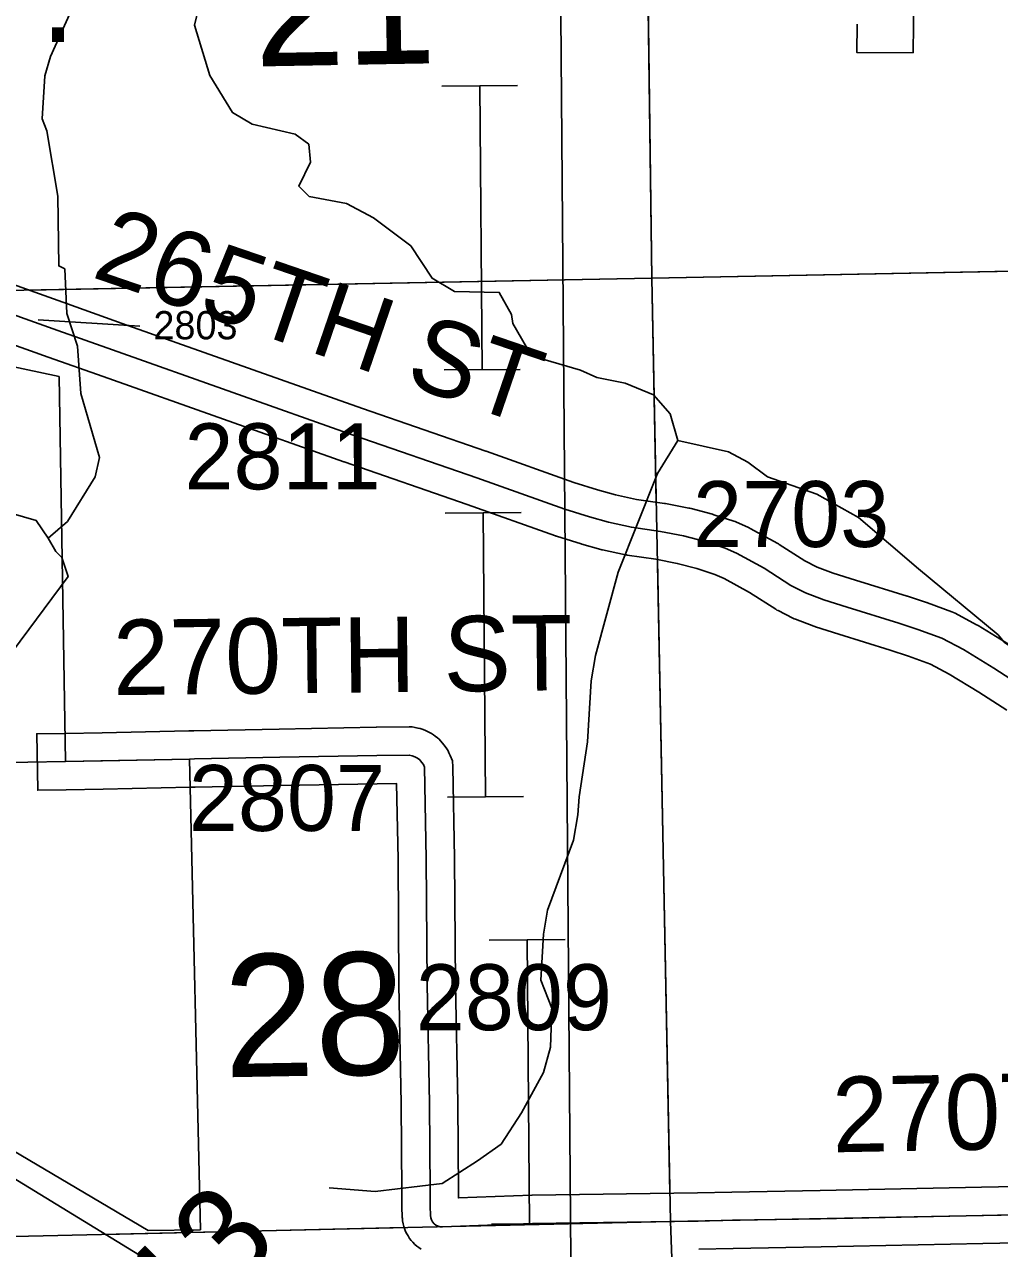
# Model space of a CAD drawing. Extents: x 23.6 to 68.7, y -63 to -29.
# Drawn here: x 47.009 to 48.044, y -50.568 to -49.268 of the extents above; entities that cross this region are included whole.
import ezdxf

# ---------------------------------------------------------------- set-up
doc = ezdxf.new("R2010")
doc.units = 0
for name, color, linetype in [('tdCoCityStreetMajor', 7, 'Continuous'), ('tdCoCorpBndry', 7, 'Continuous'), ('tdCoCorpPopTxt', 7, 'Continuous'), ('tdCoHydroRiver', 7, 'Continuous'), ('tdCoPipe', 7, 'Continuous'), ('tdCoSecRdNmbr', 7, 'Continuous'), ('tdCoSecRdTxt', 7, 'Continuous'), ('tdCoSecRteBand', 7, 'Continuous'), ('tdCoSecRteCL', 7, 'Continuous'), ('tdCoSectLine', 7, 'Continuous'), ('tdCoSectLinePart', 7, 'Continuous'), ('tdCoSectNmbr', 7, 'Continuous'), ('tdCoSurfGravel', 7, 'Continuous'), ('tdStHwyPriRefPost1', 7, 'Continuous')]:
    doc.layers.add(name, color=color, linetype=linetype)

msp = doc.modelspace()

# ---------------------------------------------------------------- linework, layer by layer
at = {"layer": 'tdCoCityStreetMajor'}
msp.add_lwpolyline([(46.9325, -50.0529), (47.0124, -50.0514), (47.0524, -50.0507)], dxfattribs=at)
at = {"layer": 'tdCoCorpBndry'}
msp.add_lwpolyline([(46.8095, -49.5915), (47.0456, -49.6419), (47.0524, -50.0507), (47.184, -50.048), (47.1957, -50.5478), (47.1403, -50.5485), (46.937, -50.4286)], dxfattribs=at)
msp.add_lwpolyline([(47.1214, -50.8004), (46.8344, -50.5559), (46.9417, -50.5533), (46.938, -50.4571), (47.194, -50.6134), (47.4984, -50.7957)], close=True, dxfattribs=at)
at = {"layer": 'tdCoHydroRiver'}
for points in [[(47.1144, -49.2111), (47.083, -49.2272), (47.0721, -49.2353), (47.0581, -49.2543), (47.0365, -49.3019), (47.0304, -49.3225), (47.0278, -49.3683), (47.0326, -49.3809), (47.0444, -49.4502), (47.0452, -49.5244), (47.0516, -49.5275), (47.0537, -49.5748), (47.0651, -49.6095), (47.0688, -49.6599), (47.0885, -49.7276), (47.084, -49.7482), (47.0545, -49.7958), (47.0342, -49.8134)], [(47.7024, -49.7098), (47.6942, -49.6815), (47.6766, -49.6611), (47.6465, -49.6488), (47.6164, -49.6429), (47.599, -49.6352), (47.553, -49.6215), (47.5419, -49.6105), (47.5274, -49.5854), (47.5257, -49.576), (47.5128, -49.5524), (47.4654, -49.5514), (47.4416, -49.5374), (47.4191, -49.503), (47.3793, -49.4734), (47.3508, -49.4579), (47.3112, -49.4505), (47.3, -49.4395), (47.3124, -49.4142), (47.3106, -49.3952), (47.2963, -49.3843), (47.2504, -49.3738), (47.2297, -49.3614), (47.2056, -49.3222), (47.1893, -49.2687), (47.1938, -49.2497)], [(47.7024, -49.7098), (47.6807, -49.7448), (47.6392, -49.8494), (47.6149, -49.9381), (47.6105, -49.965), (47.6064, -50.0297), (47.5976, -50.0882), (47.5962, -50.1072), (47.5918, -50.1341), (47.5642, -50.2086), (47.5597, -50.2339), (47.5571, -50.2828), (47.5685, -50.3127), (47.5673, -50.3538), (47.5597, -50.3807), (47.5365, -50.4236), (47.5148, -50.4569), (47.4897, -50.4746), (47.4521, -50.4987), (47.3812, -50.5073), (47.3322, -50.5032)], [(48.4058, -50.3777), (48.3898, -50.3589), (48.3545, -50.3041), (48.2986, -50.2416), (48.2665, -50.1961), (48.2552, -50.1726), (48.2488, -50.1663), (48.2183, -50.1209), (48.157, -50.0032), (48.1299, -49.9782), (48.0488, -49.9238), (48.0424, -49.916), (47.958, -49.8459), (47.8943, -49.7914), (47.8498, -49.7666), (47.7975, -49.7482), (47.7768, -49.7327), (47.7562, -49.7218), (47.7024, -49.7098)], [(47.0342, -49.8134), (47.0214, -49.7946), (46.9944, -49.787), (46.9835, -49.7935), (46.9807, -49.8266), (46.9777, -49.8456), (46.9512, -49.8743), (46.9484, -49.9107)], [(47.0342, -49.8134), (47.0423, -49.8275), (47.0486, -49.8338), (47.0552, -49.8542), (46.9961, -49.9338), (46.9681, -49.9783), (46.9355, -50.0292), (46.9152, -50.0436)]]:
    msp.add_lwpolyline(points, dxfattribs=at)
at = {"layer": 'tdCoPipe'}
for p, q in [((47.4519, -49.3335), (47.5324, -49.3328)), ((47.4543, -49.6348), (47.535, -49.6342)), ((47.4556, -49.787), (47.5361, -49.7863)), ((47.458, -50.0883), (47.5387, -50.0877)), ((47.5022, -50.2405), (47.5828, -50.2398)), ((47.5047, -50.5418), (47.5853, -50.5412))]:
    msp.add_line(p, q, dxfattribs=at)
for points in [[(47.6047, -46.6586), (47.5572, -46.6597), (47.5935, -51.1509), (47.5318, -51.225), (47.5319, -51.3484), (47.5319, -51.3484), (47.6677, -51.41), (47.7455, -57.4574)], [(47.4922, -49.3332), (47.4947, -49.6345)], [(47.4959, -49.7867), (47.4983, -50.088)], [(47.5426, -50.2402), (47.545, -50.5415)]]:
    msp.add_lwpolyline(points, dxfattribs=at)
at = {"layer": 'tdCoSecRdNmbr'}
msp.add_line((47.1312, -49.5883), (47.0235, -49.5816), dxfattribs=at)
at = {"layer": 'tdCoSecRteBand'}
for points in [[(47.9532, -49.2205), (47.9527, -49.2682), (47.9524, -49.2982)], [(47.9524, -49.2982), (47.8924, -49.2976), (47.8927, -49.2676)], [(46.8977, -49.5087), (47.0544, -49.5646), (47.1125, -49.5853), (47.3678, -49.6758), (47.4987, -49.7211), (47.4988, -49.7212), (47.4989, -49.7212), (47.5921, -49.7543), (47.6172, -49.7622), (47.6361, -49.7675), (47.6584, -49.7722), (47.6882, -49.7765), (47.6889, -49.7766), (47.6895, -49.7767), (47.7142, -49.7814), (47.7153, -49.7816), (47.7165, -49.7819), (47.7391, -49.7881), (47.7399, -49.7883), (47.7406, -49.7885), (47.7618, -49.7954), (47.7632, -49.7959), (47.7646, -49.7965), (47.7769, -49.8019), (47.7781, -49.8025), (47.7793, -49.8031), (47.8084, -49.8191), (47.8092, -49.8196), (47.81, -49.8201), (47.8374, -49.8376), (47.8502, -49.8441), (47.8673, -49.8506), (47.8911, -49.858), (47.8911, -49.858), (47.8911, -49.858), (47.9458, -49.875), (47.9461, -49.875), (47.9463, -49.8751), (47.9665, -49.8818), (47.967, -49.8819), (47.9675, -49.8821), (47.9931, -49.8915), (47.9951, -49.8922), (47.9969, -49.8932), (48.0196, -49.9053), (48.0204, -49.9057), (48.0211, -49.9061), (48.0534, -49.9259)], [(48.0516, -49.9961), (48.0218, -49.9769), (47.9906, -49.9578), (47.9706, -49.9471), (47.9473, -49.9386), (47.9278, -49.9322), (47.8733, -49.9153), (47.8487, -49.9076), (47.8478, -49.9073), (47.8469, -49.907), (47.8274, -49.8996), (47.8259, -49.899), (47.8245, -49.8983), (47.8089, -49.8904), (47.8076, -49.8898), (47.8064, -49.889), (47.7786, -49.8712), (47.7515, -49.8563), (47.7418, -49.852), (47.7227, -49.8458), (47.7018, -49.8402), (47.679, -49.8358), (47.6488, -49.8315), (47.6478, -49.8313), (47.6468, -49.8311), (47.6226, -49.8259), (47.6217, -49.8257), (47.6208, -49.8255), (47.6006, -49.8198), (47.6002, -49.8197), (47.5998, -49.8196), (47.5736, -49.8114), (47.5731, -49.8113), (47.5725, -49.8111), (47.4789, -49.7778), (47.3481, -49.7325), (47.348, -49.7324), (47.3479, -49.7324), (47.0924, -49.6419), (47.0924, -49.6419), (47.0923, -49.6419), (47.0342, -49.6211), (46.8777, -49.5652)], [(47.4299, -50.5686), (47.4275, -50.5668), (47.4255, -50.5653), (47.4231, -50.5634), (47.4211, -50.5611), (47.4195, -50.5593), (47.4175, -50.557), (47.416, -50.5543), (47.4148, -50.5522), (47.4133, -50.5496), (47.4123, -50.5467), (47.4116, -50.5443), (47.4107, -50.5414), (47.4103, -50.5384), (47.41, -50.536), (47.4099, -50.5349), (47.4099, -50.5339), (47.4095, -50.5241), (47.4095, -50.5235), (47.4095, -50.5229), (47.4095, -50.5075), (47.4088, -50.4139), (47.4064, -50.2879), (47.4064, -50.2877), (47.4064, -50.2876), (47.4054, -50.1542), (47.4039, -50.074), (47.3832, -50.0742), (47.2806, -50.0761), (47.1901, -50.0779), (47.1846, -50.078), (47.0924, -50.08), (47.0923, -50.08), (47.0923, -50.08), (47.053, -50.0807), (47.023, -50.0812), (47.0219, -50.0212), (47.0519, -50.0207), (47.0912, -50.02), (47.1834, -50.018), (47.1888, -50.0179), (47.1888, -50.0179), (47.1888, -50.0179), (47.2794, -50.0161), (47.2794, -50.0161), (47.2794, -50.0161), (47.3822, -50.0143), (47.3823, -50.0143), (47.3824, -50.0143), (47.4171, -50.0138), (47.4203, -50.0138), (47.4235, -50.0145), (47.4266, -50.0151), (47.4289, -50.0156), (47.4311, -50.0164), (47.4339, -50.0175), (47.4361, -50.0183), (47.4382, -50.0195), (47.4409, -50.021), (47.4429, -50.0222), (47.4447, -50.0236), (47.4472, -50.0256), (47.449, -50.027), (47.4506, -50.0288), (47.4527, -50.031), (47.4542, -50.0328), (47.4555, -50.0347), (47.4573, -50.0373), (47.4585, -50.0393), (47.4595, -50.0414), (47.4608, -50.0442), (47.4634, -50.0499), (47.4635, -50.0561), (47.4654, -50.1532), (47.4654, -50.1534), (47.4654, -50.1535), (47.4664, -50.2869), (47.4688, -50.413), (47.4688, -50.4132), (47.4688, -50.4134), (47.4695, -50.5072), (47.4695, -50.5073), (47.4695, -50.5074), (47.4695, -50.5141), (47.5473, -50.5112), (47.5476, -50.5112), (47.5479, -50.5112), (47.7234, -50.5086), (47.7598, -50.5078), (47.7598, -50.5078), (47.7599, -50.5078), (47.8535, -50.5061), (48.0249, -50.5026), (48.1699, -50.4997)], [(48.1709, -50.5596), (48.0261, -50.5626), (48.0261, -50.5626), (48.0261, -50.5626), (47.8546, -50.5661), (47.8546, -50.5661), (47.8546, -50.5661), (47.761, -50.5677), (47.7246, -50.5686)]]:
    msp.add_lwpolyline(points, dxfattribs=at)
at = {"layer": 'tdCoSecRteCL'}
for points in [[(46.8876, -49.5369), (47.0443, -49.5929), (47.1024, -49.6136), (47.3579, -49.7041), (47.4889, -49.7495), (47.5826, -49.7828), (47.6087, -49.7909), (47.6289, -49.7966), (47.6531, -49.8018), (47.6839, -49.8062), (47.7086, -49.8109), (47.7313, -49.8171), (47.7525, -49.824), (47.7648, -49.8294), (47.7939, -49.8454), (47.8225, -49.8637), (47.8381, -49.8716), (47.8575, -49.879), (47.8822, -49.8866), (47.9369, -49.9036), (47.9572, -49.9103), (47.9828, -49.9197), (48.0055, -49.9317), (48.0378, -49.9515), (48.0679, -49.9709)], [(47.0524, -50.0507), (47.0918, -50.05), (47.184, -50.048), (47.1894, -50.0479), (47.28, -50.0461), (47.3828, -50.0443), (47.4174, -50.0438), (47.4205, -50.0445), (47.4233, -50.0456), (47.426, -50.0471), (47.4285, -50.049), (47.4305, -50.0513), (47.4323, -50.0539), (47.4335, -50.0567), (47.4354, -50.1538), (47.4364, -50.2873), (47.4388, -50.4136), (47.4395, -50.5074), (47.4395, -50.5229), (47.4399, -50.5327), (47.4401, -50.5351), (47.4409, -50.5374), (47.4421, -50.5396), (47.4437, -50.5414), (47.4457, -50.5429), (47.4479, -50.544), (47.4503, -50.5446), (47.4527, -50.5447), (47.5483, -50.5412), (47.7239, -50.5386), (47.7604, -50.5378), (47.854, -50.5361), (48.0255, -50.5326), (48.1705, -50.5296)]]:
    msp.add_lwpolyline(points, dxfattribs=at)
at = {"layer": 'tdCoSectLine'}
for points in [[(47.6616, -48.5433), (47.6748, -49.5372)], [(47.6748, -49.5372), (48.6762, -49.5179)], [(46.6744, -49.5566), (47.6748, -49.5372)], [(47.6748, -49.5372), (47.6946, -50.539)], [(47.6946, -50.539), (48.6917, -50.5199)], [(46.6878, -50.5621), (47.6946, -50.539)], [(47.6946, -50.539), (47.7309, -51.5361)]]:
    msp.add_lwpolyline(points, dxfattribs=at)
at = {"layer": 'tdCoSectLinePart'}
for points in [[(47.6686, -49.0685), (47.6748, -49.5372)], [(47.6748, -49.5372), (48.6461, -49.5184)], [(47.0136, -49.55), (47.6748, -49.5372)], [(47.6748, -49.5372), (47.6795, -49.7753)], [(47.6807, -49.8367), (47.694, -50.5085)], [(47.0944, -50.5528), (47.4118, -50.5455)]]:
    msp.add_lwpolyline(points, dxfattribs=at)
at = {"layer": 'tdCoSurfGravel'}
for points in [[(46.4274, -49.3397), (46.4381, -49.352), (46.4506, -49.3658), (46.4659, -49.3771), (46.4894, -49.3887), (46.5261, -49.4042), (46.661, -49.4578), (46.6751, -49.4632), (46.6972, -49.4718), (46.8876, -49.5369), (47.0443, -49.5929)], [(47.0443, -49.5929), (47.1024, -49.6136), (47.3579, -49.7041), (47.4889, -49.7495), (47.5826, -49.7828), (47.6087, -49.7909), (47.6289, -49.7966), (47.6531, -49.8018), (47.6839, -49.8062), (47.7086, -49.8109), (47.7313, -49.8171), (47.7525, -49.824), (47.7648, -49.8294), (47.7939, -49.8454), (47.8225, -49.8637), (47.8381, -49.8716), (47.8575, -49.879), (47.8822, -49.8866), (47.9369, -49.9036), (47.9572, -49.9103), (47.9828, -49.9197), (48.0055, -49.9317), (48.0378, -49.9515), (48.0679, -49.9709)], [(47.184, -50.048), (47.1894, -50.0479), (47.28, -50.0461), (47.3828, -50.0443), (47.4174, -50.0438), (47.4205, -50.0445), (47.4233, -50.0456), (47.426, -50.0471), (47.4285, -50.049), (47.4305, -50.0513), (47.4323, -50.0539), (47.4335, -50.0567), (47.4354, -50.1538), (47.4364, -50.2873), (47.4388, -50.4136), (47.4395, -50.5074), (47.4395, -50.5229), (47.4399, -50.5327), (47.4401, -50.5351), (47.4409, -50.5374), (47.4421, -50.5396), (47.4437, -50.5414), (47.4457, -50.5429), (47.4479, -50.544), (47.4503, -50.5446), (47.4527, -50.5447), (47.5483, -50.5412), (47.7239, -50.5386), (47.7604, -50.5378), (47.854, -50.5361), (48.0255, -50.5326), (48.1705, -50.5296)], [(47.0524, -50.0507), (47.0918, -50.05), (47.184, -50.048)]]:
    msp.add_lwpolyline(points, dxfattribs=at)

# ---------------------------------------------------------------- texts
at = {"layer": 'tdCoCorpPopTxt'}
msp.add_text('POP.', height=0.1, dxfattribs=at).set_placement((46.7435, -49.2864))
at = {"layer": 'tdCoSecRdNmbr'}
for s, height, rotation, p in [('2803', 0.03, 0.0367, (47.1458, -49.6023)), ('2811', 0.07, 0.0367, (47.1788, -49.7616)), ('2703', 0.07, 0.0371, (47.7186, -49.8229)), ('2807', 0.07, 0.0367, (47.1834, -50.1244)), ('2809', 0.07, 0.0367, (47.4243, -50.336))]:
    msp.add_text(s, height=height, rotation=rotation, dxfattribs=at).set_placement(p)
at = {"layer": 'tdCoSecRdTxt'}
for s, rotation, p in [('265TH ST', 341.0916, (47.0788, -49.5357)), ('270TH ST', 0.6279, (47.1033, -49.9802)), ('270TH ST', 1.0843, (47.867, -50.4657))]:
    msp.add_text(s, height=0.08, rotation=rotation, dxfattribs=at).set_placement(p)
at = {"layer": 'tdCoSectNmbr'}
for s, p in [('21', (47.2533, -49.3126)), ('28', (47.2212, -50.386))]:
    msp.add_text(s, height=0.13, rotation=1.0367, dxfattribs=at).set_placement(p)
at = {"layer": 'tdStHwyPriRefPost1'}
msp.add_text('‒‒13', height=0.1, rotation=45, dxfattribs=at).set_placement((47.0703, -50.7726))

doc.saveas('drawing.dxf')
